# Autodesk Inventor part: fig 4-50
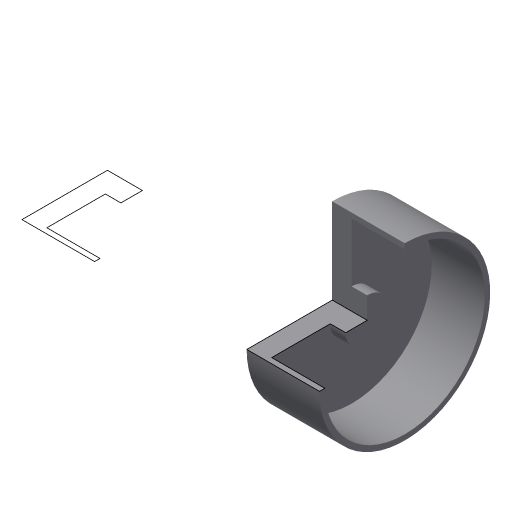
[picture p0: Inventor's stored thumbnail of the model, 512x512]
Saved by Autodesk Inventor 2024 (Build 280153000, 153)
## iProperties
Created: 2004-05
Part Number: fig 4-50
Document SubType Name: Modeling
Designer: CADCIM Technologies
Manufacturer: Standard
Standards Organization: Custom
Density: 1 g/cm^3
Material: Generic
Appearance: Default
Author: CADCIM Technologies
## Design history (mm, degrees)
sketch "Sketch1"
  geometry: L1 (30.083, 49.92)-(16.646, 49.92); L2 (16.646, 49.92)-(16.646, 17.104); L3 (16.646, 17.104)-(44.553, 17.104); L4 (44.553, 17.104)-(44.553, 19.171); L5 (44.553, 19.171)-(24.139, 19.171); L6 (24.139, 19.171)-(24.139, 41.652); L7 (24.139, 41.652)-(30.083, 41.652); L8 (30.083, 41.652)-(30.083, 49.92); L9 (116.437, 49.92)-(103, 49.92); L10 (103, 49.92)-(103, 17.104); L11 (103, 17.104)-(130.907, 17.104); L12 (130.907, 17.104)-(130.907, 19.171); L13 (130.907, 19.171)-(110.494, 19.171); L14 (110.494, 19.171)-(110.494, 41.652); L15 (110.494, 41.652)-(116.437, 41.652); L16 (116.437, 41.652)-(116.437, 49.92)
  constraints: 32 end point, 2 horizontal
revolve "Revolution1" sketch "Sketch1" stored, may be unused: angle "d0" = 270 deg
body "Solid1"
